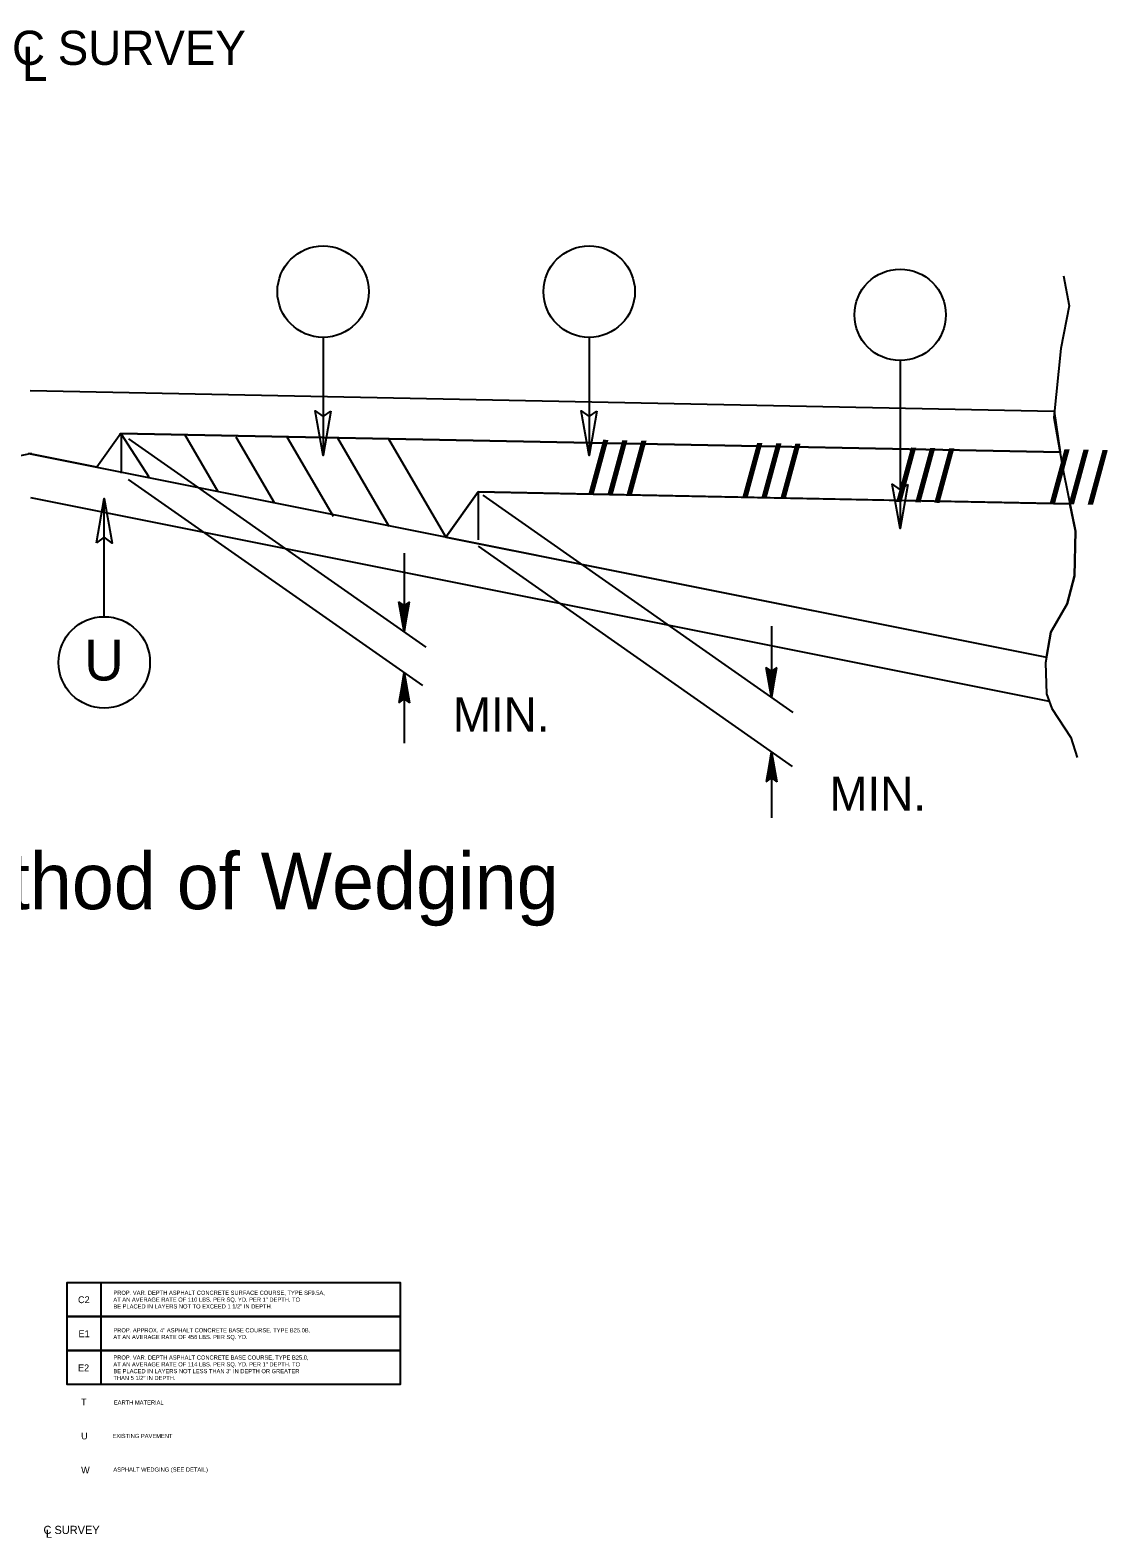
# Model space of a CAD drawing. Extents: x 1818040 to 1825768, y 638918 to 648046.
# Drawn here: x 1824344 to 1825768, y 641008 to 643000 of the extents above; entities that cross this region are included whole.
import ezdxf

# ---------------------------------------------------------------- set-up
doc = ezdxf.new("R2010")
doc.units = 0
for name, color, linetype in [('Prop Pavement Schedule Description CELL', 7, 'Continuous'), ('Typical Detail Wedge2 CELL', 7, 'Continuous'), ('Typical ID Circle CELL', 7, 'Continuous'), ('Typical Terminator CELL', 7, 'Continuous'), ('Typical Text Centerline CELL', 7, 'Continuous'), ('Typical Text General CELL', 7, 'Continuous'), ('Typical Text ID Circle CELL', 7, 'Continuous')]:
    doc.layers.add(name, color=color, linetype=linetype)

msp = doc.modelspace()

# ---------------------------------------------------------------- linework, layer by layer
at = {"layer": 'Prop Pavement Schedule Description CELL'}
for points in [[(1824437.8, 641300.6), (1824392.8, 641300.6), (1824392.8, 641345.6), (1824832.8, 641345.6), (1824832.8, 641300.6), (1824437.8, 641300.6), (1824437.8, 641345.6)], [(1824437.8, 641255.6), (1824392.8, 641255.6), (1824392.8, 641300.6), (1824832.8, 641300.6), (1824832.8, 641255.6), (1824437.8, 641255.6), (1824437.8, 641300.6)], [(1824437.8, 641210.6), (1824392.8, 641210.6), (1824392.8, 641255.6), (1824832.8, 641255.6), (1824832.8, 641210.6), (1824437.8, 641210.6), (1824437.8, 641255.6)]]:
    msp.add_lwpolyline(points, dxfattribs=at)
at = {"layer": 'Typical Detail Wedge2 CELL'}
for p, q in [((1824343.8, 642523.5), (1825696.6, 642496.5)), ((1824343.9, 642523.5), (1825696.6, 642496.5)), ((1825696.6, 642496.5), (1825704.4, 642442.1)), ((1824463.5, 642466.9), (1824432.1, 642422.4)), ((1824463.5, 642466.9), (1824432.1, 642422.4)), ((1824461.5, 642465.9), (1824463.4, 642465.8)), ((1824463.5, 642466.9), (1825704.4, 642442.1)), ((1825704.4, 642442.1), (1824463.5, 642466.9)), ((1824501, 642409.1), (1824464.3, 642466.4)), ((1824464.3, 642466.4), (1824464.3, 642414.5)), ((1824547.7, 642465.8), (1824591.9, 642390.2)), ((1824473.8, 642459.7), (1824866.5, 642184.7)), ((1824615.6, 642462.4), (1824666.2, 642375.7)), ((1824682.9, 642462.5), (1824744, 642357.8)), ((1824749.8, 642461.2), (1824817.9, 642344.4)), ((1824817.4, 642459.8), (1824893, 642330)), ((1824345.8, 642440.3), (1823001.2, 642171.3)), ((1824341.8, 642440.3), (1825686.5, 642171.3)), ((1824432.1, 642422.4), (1824341.8, 642440.3)), ((1824473.3, 642406.3), (1824862.1, 642134)), ((1824935.6, 642389.6), (1824893, 642330)), ((1824893.1, 642330), (1824935.6, 642389.6)), ((1824935.6, 642389.6), (1825717.5, 642374)), ((1824935.6, 642389.6), (1824935.6, 642326.2)), ((1825493.2, 642378.5), (1824935.6, 642389.6)), ((1824941.9, 642385.2), (1825351.4, 642098.5)), ((1824344.3, 642382.4), (1825690, 642113.2)), ((1825717.5, 642374), (1825493.2, 642378.5)), ((1824893, 642330), (1825071.8, 642294.3)), ((1824837.8, 642308.8), (1824837.8, 642204.8)), ((1824935.6, 642318), (1825350.7, 642027.2)), ((1825071.8, 642294.3), (1825686.5, 642171.3)), ((1824837.8, 642204.8), (1824830.8, 642244.6)), ((1824837.8, 642239.5), (1824830.8, 642244.6)), ((1824837.8, 642204.8), (1824831.8, 642243.9)), ((1824832.8, 642243.1), (1824837.8, 642204.8)), ((1824837.8, 642204.8), (1824833.8, 642242.4)), ((1824834.8, 642241.6), (1824837.8, 642204.8)), ((1824837.8, 642204.8), (1824835.8, 642240.9)), ((1824836.7, 642240.2), (1824837.8, 642204.8)), ((1824837.8, 642204.8), (1824844.8, 642244.6)), ((1824844.8, 642244.6), (1824837.8, 642239.5)), ((1824843.8, 642243.9), (1824837.8, 642204.8)), ((1824837.8, 642204.8), (1824842.8, 642243.1)), ((1824841.8, 642242.4), (1824837.8, 642204.8)), ((1824837.8, 642204.8), (1824840.8, 642241.6)), ((1824839.8, 642240.9), (1824837.8, 642204.8)), ((1824837.8, 642204.8), (1824838.8, 642240.2)), ((1824837.8, 642239.5), (1824837.8, 642204.8)), ((1825323.2, 642212.2), (1825323.2, 642118.2)), ((1824837.8, 642151), (1824830.8, 642111.2)), ((1824831.8, 642112), (1824837.8, 642151)), ((1824837.8, 642151), (1824832.8, 642112.7)), ((1824833.8, 642113.5), (1824837.8, 642151)), ((1824837.8, 642151), (1824834.8, 642114.2)), ((1824835.8, 642114.9), (1824837.8, 642151)), ((1824837.8, 642151), (1824836.7, 642115.7)), ((1824837.8, 642151), (1824837.8, 642058)), ((1824837.8, 642151), (1824844.8, 642111.2)), ((1824837.8, 642116.4), (1824837.8, 642151)), ((1824838.8, 642115.7), (1824837.8, 642151)), ((1824837.8, 642151), (1824839.8, 642114.9)), ((1824840.8, 642114.2), (1824837.8, 642151)), ((1824837.8, 642151), (1824841.8, 642113.5)), ((1824842.8, 642112.7), (1824837.8, 642151)), ((1824837.8, 642151), (1824843.8, 642112)), ((1825323.2, 642118.2), (1825316.2, 642157.9)), ((1825323.2, 642152.8), (1825316.2, 642157.9)), ((1825323.2, 642118.2), (1825317.2, 642157.2)), ((1825318.2, 642156.5), (1825323.2, 642118.2)), ((1825323.2, 642118.2), (1825319.2, 642155.8)), ((1825320.2, 642155), (1825323.2, 642118.2)), ((1825323.2, 642118.2), (1825321.2, 642154.3)), ((1825322.2, 642153.5), (1825323.2, 642118.2)), ((1825323.2, 642118.2), (1825330.2, 642157.9)), ((1825330.2, 642157.9), (1825323.2, 642152.8)), ((1825329.2, 642157.2), (1825323.2, 642118.2)), ((1825323.2, 642118.2), (1825328.2, 642156.5)), ((1825327.2, 642155.8), (1825323.2, 642118.2)), ((1825323.2, 642118.2), (1825326.2, 642155)), ((1825325.2, 642154.3), (1825323.2, 642118.2)), ((1825323.2, 642118.2), (1825324.2, 642153.5)), ((1825323.2, 642152.8), (1825323.2, 642118.2)), ((1824830.8, 642111.2), (1824837.8, 642116.4)), ((1824837.8, 642116.4), (1824844.8, 642111.2)), ((1825323.2, 642046.5), (1825316.2, 642006.7)), ((1825317.2, 642007.5), (1825323.2, 642046.5)), ((1825323.2, 642046.5), (1825318.2, 642008.2)), ((1825319.2, 642008.9), (1825323.2, 642046.5)), ((1825323.2, 642046.5), (1825320.2, 642009.7)), ((1825321.2, 642010.4), (1825323.2, 642046.5)), ((1825323.2, 642046.5), (1825322.2, 642011.1)), ((1825323.2, 642046.5), (1825323.2, 641959.2)), ((1825323.2, 642046.5), (1825330.2, 642006.7)), ((1825323.2, 642011.9), (1825323.2, 642046.5)), ((1825324.2, 642011.1), (1825323.2, 642046.5)), ((1825323.2, 642046.5), (1825325.2, 642010.4)), ((1825326.2, 642009.7), (1825323.2, 642046.5)), ((1825323.2, 642046.5), (1825327.2, 642008.9)), ((1825328.2, 642008.2), (1825323.2, 642046.5)), ((1825323.2, 642046.5), (1825329.2, 642007.5)), ((1825316.2, 642006.7), (1825323.2, 642011.9)), ((1825323.2, 642011.9), (1825330.2, 642006.7))]:
    msp.add_line(p, q, dxfattribs=at)
for points in [[(1825709.1, 642675), (1825716.4, 642635.4), (1825705.6, 642579), (1825696, 642487.8), (1825709.1, 642415.8), (1825724.8, 642337.8), (1825723.6, 642279), (1825713.9, 642241.8), (1825692.3, 642204.6), (1825685.2, 642163.8), (1825686.3, 642123), (1825693.5, 642103.8), (1825718.7, 642065.4), (1825727.1, 642039)], [(1825686.5, 642171.3), (1825692.3, 642204.6), (1825713.9, 642241.8), (1825723.6, 642279), (1825724.8, 642337.8), (1825717.5, 642374)]]:
    msp.add_lwpolyline(points, dxfattribs=at)
at = {"layer": 'Typical ID Circle CELL'}
for p, q in [((1824730.9, 642593.8), (1824730.9, 642437.7)), ((1825082.4, 642593.8), (1825082.4, 642437.7)), ((1825493.2, 642563.2), (1825493.2, 642341.2)), ((1824441.7, 642224.9), (1824441.7, 642381.1))]:
    msp.add_line(p, q, dxfattribs=at)
for centre in [(1824730.9, 642654.2), (1825082.4, 642654.2), (1825493.2, 642623.6), (1824441.7, 642164.5)]:
    msp.add_circle(centre, 60.4, dxfattribs=at)
at = {"layer": 'Typical Terminator CELL'}
for points in [[(1824741, 642496.3), (1824730.9, 642437.7), (1824720.5, 642496.6), (1824730.9, 642489.1)], [(1824741, 642496.3), (1824730.9, 642437.7), (1824720.5, 642496.6), (1824730.9, 642489.1)], [(1825092.5, 642496.3), (1825082.4, 642437.7), (1825072, 642496.6), (1825082.4, 642489.1)], [(1825092.5, 642496.3), (1825082.4, 642437.7), (1825072, 642496.6), (1825082.4, 642489.1)], [(1825503.3, 642399.7), (1825493.2, 642341.2), (1825482.8, 642400.1), (1825493.2, 642392.6)], [(1824431.6, 642322.5), (1824441.7, 642381.1), (1824452.1, 642322.2), (1824441.7, 642329.7)], [(1824431.6, 642322.5), (1824441.7, 642381.1), (1824452.1, 642322.2), (1824441.7, 642329.7)]]:
    msp.add_lwpolyline(points, close=True, dxfattribs=at)

# ---------------------------------------------------------------- texts
at = {"layer": 'Prop Pavement Schedule Description CELL'}
for s, height, p in [('PROP. VAR. DEPTH ASPHALT CONCRETE SURFACE COURSE, TYPE SF9.5A,', 5.5, (1824453.8, 641329.1)), ('C2', 8.98, (1824407.1, 641318.2)), ('AT AN AVERAGE RATE OF 110 LBS. PER SQ. YD. PER 1" DEPTH. TO', 5.5, (1824453.8, 641320.1)), ('BE PLACED IN LAYERS NOT TO EXCEED 1 1/2" IN DEPTH.', 5.5, (1824453.8, 641311.1)), ('E1', 8.98, (1824407.8, 641273.2)), ('AT AN AVERAGE RATE OF 456 LBS. PER SQ. YD.', 5.5, (1824453.8, 641270.7)), ('PROP. APPROX. 4" ASPHALT CONCRETE BASE COURSE, TYPE B25.0B,', 5.5, (1824453.8, 641279.6)), ('E2', 8.98, (1824407.1, 641228.2)), ('AT AN AVERAGE RATE OF 114 LBS. PER SQ. YD. PER 1" DEPTH. TO', 5.5, (1824453.8, 641234.6)), ('PROP. VAR. DEPTH ASPHALT CONCRETE BASE COURSE, TYPE B25.0,', 5.5, (1824453.8, 641243.6)), ('BE PLACED IN LAYERS NOT LESS THAN 3" IN DEPTH OR GREATER', 5.5, (1824453.8, 641225.6)), ('THAN 5 1/2" IN DEPTH.', 5.5, (1824453.8, 641216.6)), ('T', 8.98, (1824411.2, 641183.2)), ('EARTH MATERIAL', 5.5, (1824454.4, 641184.2)), ('U', 8.98, (1824411.2, 641138.2)), ('EXISTING PAVEMENT', 5.5, (1824452.6, 641140)), ('W', 8.98, (1824411.2, 641093.2)), ('ASPHALT WEDGING (SEE DETAIL)', 5.5, (1824453.8, 641095.6))]:
    msp.add_text(s, height=height, dxfattribs=at).set_placement(p)
at = {"layer": 'Typical Detail Wedge2 CELL'}
for height, rotation, p in [(67.82, 358.8553, (1825081.2, 642387.5)), (67.81, 358.8536, (1825284.6, 642383.3)), (67.84, 358.8554, (1825487.8, 642377.3)), (67.84, 358.8537, (1825690.5, 642374.9))]:
    msp.add_text('/// ', height=height, rotation=rotation, dxfattribs=at).set_placement(p)
for p in [(1824902.3, 642073.2), (1825399.8, 641968.5)]:
    msp.add_text('MIN.', height=45.19, dxfattribs=at).set_placement(p)
at = {"layer": 'Typical Text Centerline CELL'}
for s, height, p in [('C SURVEY ', 45.19, (1824319.9, 642953.7)), ('L', 45.2, (1824333.1, 642932.6)), ('C SURVEY ', 10.85, (1824361.5, 641013.2)), ('L', 10.8, (1824364.7, 641008.2))]:
    msp.add_text(s, height=height, dxfattribs=at).set_placement(p)
at = {"layer": 'Typical Text General CELL'}
msp.add_text('Detail Showing Method of Wedging', height=74.597, dxfattribs=at).set_placement((1823484, 641838.5))
at = {"layer": 'Typical Text ID Circle CELL'}
msp.add_text('U', height=54.1, dxfattribs=at).set_placement((1824415.3, 642140.6))

doc.saveas('drawing.dxf')
